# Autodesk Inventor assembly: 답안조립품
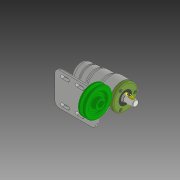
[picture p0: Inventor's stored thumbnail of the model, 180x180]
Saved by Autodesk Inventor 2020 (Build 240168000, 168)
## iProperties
Created: 2021-10
Part Number: 답안조립품
Document SubType Name: Assembly
Designer: user
Author: user
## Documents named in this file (12)
- C:\Users\user\Desktop\711007V1005\답안조립품.iam
- C:\Users\user\Desktop\711007V1005\V벨트풀리.ipt
- C:\Users\user\Desktop\711007V1005\멈춤나사 M3.ipt
- C:\Users\user\Desktop\711007V1005\베어링 6004.ipt
- C:\Users\user\Desktop\711007V1005\베어링 51202.ipt
- C:\Users\user\Desktop\711007V1005\본체.ipt
- C:\Users\user\Desktop\711007V1005\볼트 M4.ipt
- C:\Users\user\Desktop\711007V1005\어댑터슬리브.ipt
- C:\Users\user\Desktop\711007V1005\오일 실 20x35x7.ipt
- C:\Users\user\Desktop\711007V1005\축.ipt
- C:\Users\user\Desktop\711007V1005\커버.ipt
- C:\Users\user\Desktop\711007V1005\키 5x5.ipt
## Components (1 placed, 1 different names)
1. V벨트풀리:1
